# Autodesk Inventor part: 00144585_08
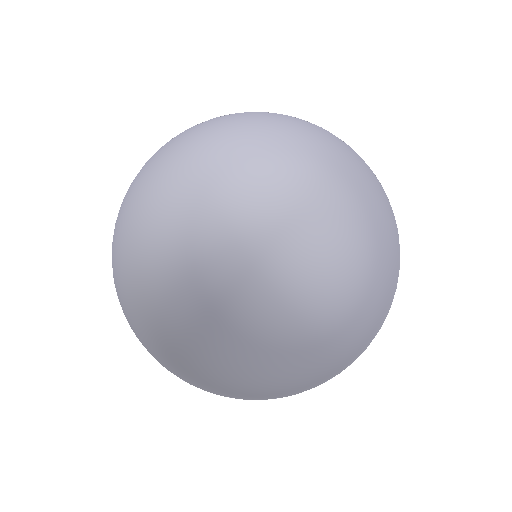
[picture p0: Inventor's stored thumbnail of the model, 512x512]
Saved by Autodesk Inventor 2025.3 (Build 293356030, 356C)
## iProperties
Created: 2021-02
Part Number: 00144585_08
Material: Generico
Document SubType Name: Modeling
Designer: R5800u
Density: 1 g/cm^3
Appearance: Default
Author: TraceParts
Sending System: SolidWorks 2021
Last Author: Albert
Last Saved: 2021-07-28
IsFastener: 1
TYPE: CATASM
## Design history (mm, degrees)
feature "Imported1"
node "Solido1"
